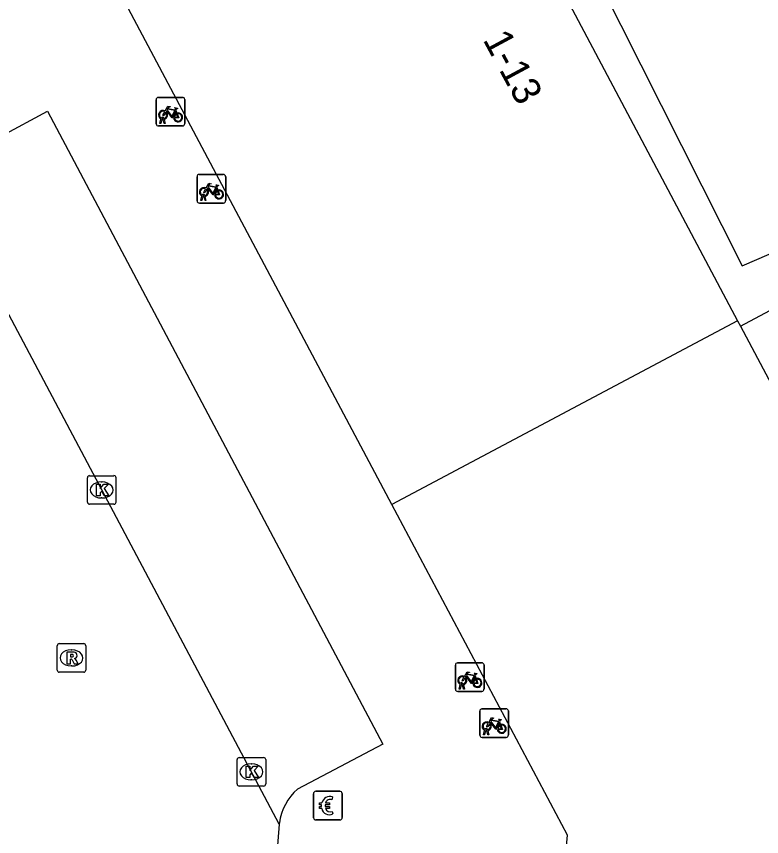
# Model space of a CAD drawing. Extents: x 160304 to 160954, y 383686 to 384161.
# Drawn here: x 160831.95 to 160858.01, y 383857.97 to 383886.65 of the extents above; entities that cross this region are included whole.
import ezdxf

# ---------------------------------------------------------------- set-up
doc = ezdxf.new("R2010")
doc.units = 0
for name, color, linetype in [('IMGEO_Betaalautomaat', 7, 'Continuous'), ('IMGEO_Fietsenrek', 7, 'Continuous'), ('IMGEO_Groenvoorziening', 7, 'Continuous'), ('IMGEO_Kolk', 7, 'Continuous'), ('IMGEO_Pand', 7, 'Continuous'), ('IMGEO_Pand_nummerreeks', 7, 'Continuous'), ('IMGEO_Rijbaan_lokaal_open', 7, 'Continuous'), ('IMGEO_Rioolput', 7, 'Continuous'), ('IMGEO_Voetpad_open', 7, 'Continuous')]:
    doc.layers.add(name, color=color, linetype=linetype)

msp = doc.modelspace()

# ---------------------------------------------------------------- linework, layer by layer
at = {"layer": 'IMGEO_Betaalautomaat'}
for p, q in [((160842.341, 383858.628), (160842.341, 383859.469)), ((160842.341, 383859.469), (160842.341, 383858.628)), ((160842.416, 383859.552), (160843.257, 383859.552)), ((160843.257, 383859.552), (160842.416, 383859.552)), ((160843.34, 383859.478), (160843.34, 383858.637)), ((160843.34, 383858.637), (160843.34, 383859.478)), ((160843.003, 383859.357), (160842.986, 383859.257)), ((160842.624, 383859.016), (160842.624, 383859.084)), ((160842.745, 383859.084), (160842.745, 383859.016)), ((160842.99, 383858.851), (160843.012, 383858.764)), ((160843.266, 383858.553), (160842.425, 383858.553)), ((160842.425, 383858.553), (160843.266, 383858.553))]:
    msp.add_line(p, q, dxfattribs=at)
for points in [[(160842.624, 383859.084), (160842.555, 383859.084), (160842.555, 383859.153), (160842.634, 383859.153)], [(160842.629, 383858.947), (160842.555, 383858.947), (160842.555, 383859.016), (160842.624, 383859.016)], [(160842.756, 383859.153), (160842.903, 383859.153), (160842.903, 383859.084), (160842.745, 383859.084)], [(160842.745, 383859.016), (160842.903, 383859.016), (160842.903, 383858.947), (160842.759, 383858.947)]]:
    msp.add_lwpolyline(points, dxfattribs=at)
for centre, radius, start, end in [((160842.419, 383859.475), 0.0779, 92.4484, 184.2845), ((160842.419, 383859.475), 0.0779, 92.4484, 184.2845), ((160843.263, 383859.475), 0.0779, 2.4484, 94.2845), ((160843.263, 383859.475), 0.0779, 2.4484, 94.2845), ((160842.917, 383859.077), 0.293, 73.014, 165.0139), ((160842.923, 383859.09), 0.179, 69.3236, 159.5683), ((160842.89, 383859.002), 0.267, 191.8096, 297.0389), ((160842.923, 383859.017), 0.179, 202.7625, 291.8693), ((160842.419, 383858.631), 0.0779, 182.4484, 274.2845), ((160842.419, 383858.631), 0.0779, 182.4484, 274.2845), ((160843.263, 383858.631), 0.0779, 272.4484, 4.2845), ((160843.263, 383858.631), 0.0779, 272.4484, 4.2845)]:
    msp.add_arc(centre, radius, start, end, dxfattribs=at)
at = {"layer": 'IMGEO_Fietsenrek'}
for p, q in [((160836.838, 383882.893), (160836.838, 383883.734)), ((160836.838, 383883.734), (160836.838, 383882.893)), ((160836.913, 383883.818), (160837.754, 383883.818)), ((160837.754, 383883.818), (160836.913, 383883.818)), ((160837.838, 383883.743), (160837.838, 383882.902)), ((160837.838, 383882.902), (160837.838, 383883.743)), ((160837.525, 383883.367), (160837.561, 383883.272)), ((160836.965, 383882.902), (160837.004, 383883.062)), ((160837.034, 383883.05), (160836.999, 383882.902)), ((160837.076, 383883.074), (160837.075, 383883.078)), ((160837.117, 383882.902), (160837.083, 383883.044)), ((160837.107, 383883.085), (160837.108, 383883.078)), ((160837.115, 383883.048), (160837.15, 383882.902)), ((160837.763, 383882.818), (160836.922, 383882.818)), ((160836.922, 383882.818), (160837.763, 383882.818)), ((160836.999, 383882.902), (160836.965, 383882.902)), ((160837.15, 383882.902), (160837.117, 383882.902)), ((160838.268, 383880.199), (160838.268, 383881.04)), ((160838.268, 383881.04), (160838.268, 383880.199)), ((160838.343, 383881.124), (160839.184, 383881.124)), ((160839.184, 383881.124), (160838.343, 383881.124)), ((160839.268, 383881.049), (160839.268, 383880.208)), ((160839.268, 383880.208), (160839.268, 383881.049)), ((160838.955, 383880.673), (160838.991, 383880.578)), ((160839.193, 383880.124), (160838.352, 383880.124)), ((160838.352, 383880.124), (160839.193, 383880.124)), ((160838.395, 383880.208), (160838.434, 383880.368)), ((160838.429, 383880.208), (160838.395, 383880.208)), ((160838.464, 383880.356), (160838.429, 383880.208)), ((160838.506, 383880.38), (160838.505, 383880.384)), ((160838.547, 383880.208), (160838.513, 383880.35)), ((160838.537, 383880.391), (160838.538, 383880.384)), ((160838.545, 383880.354), (160838.58, 383880.208)), ((160838.58, 383880.208), (160838.547, 383880.208)), ((160847.303, 383863.121), (160847.303, 383863.962)), ((160847.303, 383863.962), (160847.303, 383863.121)), ((160847.378, 383864.046), (160848.219, 383864.046)), ((160848.219, 383864.046), (160847.378, 383864.046)), ((160848.303, 383863.971), (160848.303, 383863.13)), ((160848.303, 383863.13), (160848.303, 383863.971)), ((160847.99, 383863.595), (160848.026, 383863.5)), ((160847.43, 383863.13), (160847.469, 383863.29)), ((160847.499, 383863.278), (160847.464, 383863.13)), ((160847.541, 383863.302), (160847.54, 383863.306)), ((160847.582, 383863.13), (160847.548, 383863.272)), ((160847.572, 383863.313), (160847.573, 383863.306)), ((160847.58, 383863.276), (160847.615, 383863.13)), ((160848.228, 383863.046), (160847.387, 383863.046)), ((160847.387, 383863.046), (160848.228, 383863.046)), ((160847.464, 383863.13), (160847.43, 383863.13)), ((160847.615, 383863.13), (160847.582, 383863.13)), ((160848.156, 383861.513), (160848.156, 383862.354)), ((160848.156, 383862.354), (160848.156, 383861.513)), ((160848.231, 383862.438), (160849.072, 383862.438)), ((160849.072, 383862.438), (160848.231, 383862.438)), ((160849.156, 383862.363), (160849.156, 383861.522)), ((160849.156, 383861.522), (160849.156, 383862.363)), ((160848.843, 383861.987), (160848.879, 383861.892)), ((160848.283, 383861.522), (160848.322, 383861.682)), ((160848.317, 383861.522), (160848.283, 383861.522)), ((160848.352, 383861.67), (160848.317, 383861.522)), ((160848.394, 383861.694), (160848.393, 383861.698)), ((160848.435, 383861.522), (160848.401, 383861.664)), ((160848.425, 383861.705), (160848.426, 383861.698)), ((160848.433, 383861.668), (160848.468, 383861.522)), ((160848.468, 383861.522), (160848.435, 383861.522)), ((160849.081, 383861.438), (160848.24, 383861.438)), ((160848.24, 383861.438), (160849.081, 383861.438))]:
    msp.add_line(p, q, dxfattribs=at)
for points in [[(160837.172, 383883.292), (160837.12, 383883.202), (160837.08, 383883.177), (160837.081, 383883.224), (160837.136, 383883.318)], [(160837.151, 383883.344), (160837.246, 383883.508), (160837.332, 383883.494), (160837.334, 383883.485), (160837.278, 383883.474), (160837.251, 383883.429), (160837.507, 383883.388)], [(160837.447, 383883.1), (160837.397, 383883.1), (160837.206, 383883.351), (160837.187, 383883.319)], [(160837.494, 383883.363), (160837.237, 383883.404), (160837.22, 383883.375), (160837.387, 383883.155), (160837.494, 383883.363)], [(160837.542, 383883.265), (160837.512, 383883.342), (160837.403, 383883.124), (160837.446, 383883.124)], [(160837.507, 383883.388), (160837.532, 383883.437), (160837.526, 383883.441), (160837.503, 383883.445), (160837.491, 383883.452), (160837.49, 383883.455), (160837.492, 383883.46), (160837.587, 383883.445), (160837.589, 383883.435), (160837.579, 383883.422), (160837.567, 383883.416), (160837.553, 383883.422), (160837.525, 383883.367)], [(160837.476, 383883.124), (160837.596, 383883.123), (160837.552, 383883.237)], [(160837.572, 383883.244), (160837.627, 383883.099), (160837.477, 383883.099)], [(160838.581, 383880.65), (160838.676, 383880.814), (160838.762, 383880.8), (160838.764, 383880.791), (160838.708, 383880.78), (160838.681, 383880.735), (160838.937, 383880.694)], [(160838.924, 383880.669), (160838.667, 383880.71), (160838.65, 383880.681), (160838.817, 383880.461), (160838.924, 383880.669)], [(160838.937, 383880.694), (160838.962, 383880.743), (160838.956, 383880.747), (160838.933, 383880.751), (160838.921, 383880.758), (160838.92, 383880.761), (160838.922, 383880.766), (160839.017, 383880.751), (160839.019, 383880.741), (160839.009, 383880.728), (160838.997, 383880.722), (160838.983, 383880.728), (160838.955, 383880.673)], [(160838.602, 383880.598), (160838.55, 383880.508), (160838.51, 383880.483), (160838.511, 383880.53), (160838.566, 383880.624)], [(160838.877, 383880.406), (160838.827, 383880.406), (160838.636, 383880.657), (160838.617, 383880.625)], [(160838.972, 383880.571), (160838.942, 383880.648), (160838.833, 383880.43), (160838.876, 383880.43)], [(160838.906, 383880.43), (160839.026, 383880.429), (160838.982, 383880.543)], [(160839.002, 383880.55), (160839.057, 383880.405), (160838.907, 383880.405)], [(160847.637, 383863.52), (160847.585, 383863.43), (160847.545, 383863.405), (160847.546, 383863.452), (160847.601, 383863.546)], [(160847.616, 383863.572), (160847.711, 383863.736), (160847.797, 383863.722), (160847.799, 383863.713), (160847.743, 383863.702), (160847.716, 383863.657), (160847.972, 383863.616)], [(160847.912, 383863.328), (160847.862, 383863.328), (160847.671, 383863.579), (160847.652, 383863.547)], [(160847.959, 383863.591), (160847.702, 383863.632), (160847.685, 383863.603), (160847.852, 383863.383), (160847.959, 383863.591)], [(160848.007, 383863.493), (160847.977, 383863.57), (160847.868, 383863.352), (160847.911, 383863.352)], [(160847.972, 383863.616), (160847.997, 383863.665), (160847.991, 383863.669), (160847.968, 383863.673), (160847.956, 383863.68), (160847.955, 383863.683), (160847.957, 383863.688), (160848.052, 383863.673), (160848.054, 383863.663), (160848.044, 383863.65), (160848.032, 383863.644), (160848.018, 383863.65), (160847.99, 383863.595)], [(160847.941, 383863.352), (160848.061, 383863.351), (160848.017, 383863.465)], [(160848.037, 383863.472), (160848.092, 383863.327), (160847.942, 383863.327)], [(160848.469, 383861.964), (160848.564, 383862.128), (160848.65, 383862.114), (160848.652, 383862.105), (160848.596, 383862.094), (160848.569, 383862.049), (160848.825, 383862.008)], [(160848.825, 383862.008), (160848.85, 383862.057), (160848.844, 383862.061), (160848.821, 383862.065), (160848.809, 383862.072), (160848.808, 383862.075), (160848.81, 383862.08), (160848.905, 383862.065), (160848.907, 383862.055), (160848.897, 383862.042), (160848.885, 383862.036), (160848.871, 383862.042), (160848.843, 383861.987)], [(160848.49, 383861.912), (160848.438, 383861.822), (160848.398, 383861.797), (160848.399, 383861.844), (160848.454, 383861.938)], [(160848.765, 383861.72), (160848.715, 383861.72), (160848.524, 383861.971), (160848.505, 383861.939)], [(160848.812, 383861.983), (160848.555, 383862.024), (160848.538, 383861.995), (160848.705, 383861.775), (160848.812, 383861.983)], [(160848.86, 383861.885), (160848.83, 383861.962), (160848.721, 383861.744), (160848.764, 383861.744)], [(160848.794, 383861.744), (160848.914, 383861.743), (160848.87, 383861.857)], [(160848.89, 383861.864), (160848.945, 383861.719), (160848.795, 383861.719)]]:
    msp.add_lwpolyline(points, dxfattribs=at)
for centre, radius, start, end in [((160836.916, 383883.74), 0.0779, 92.4484, 184.2845), ((160836.916, 383883.74), 0.0779, 92.4484, 184.2845), ((160837.76, 383883.74), 0.0779, 2.4484, 94.2845), ((160837.76, 383883.74), 0.0779, 2.4484, 94.2845), ((160837.078, 383883.203), 0.159, 62.6766, 242.1369), ((160837.078, 383883.203), 0.129, 63.3192, 238.903), ((160837.078, 383883.203), 0.129, 283.6043, 43.4302), ((160837.078, 383883.203), 0.159, 283.5766, 46.6042), ((160837.605, 383883.119), 0.159, 187.0065, 105.7708), ((160837.058, 383883.074), 0.0499, 12.8025, 158.6934), ((160837.078, 383883.203), 0.159, 253.9967, 271.7867), ((160837.058, 383883.074), 0.0174, 12.8025, 163.4502), ((160837.078, 383883.203), 0.129, 253.415, 269.0204), ((160837.605, 383883.119), 0.159, 113.3408, 178.3217), ((160837.605, 383883.119), 0.129, 113.923, 177.9556), ((160837.605, 383883.119), 0.129, 188.6715, 104.5883), ((160836.916, 383882.896), 0.0779, 182.4484, 274.2845), ((160836.916, 383882.896), 0.0779, 182.4484, 274.2845), ((160837.76, 383882.896), 0.0779, 272.4484, 4.2845), ((160837.76, 383882.896), 0.0779, 272.4484, 4.2845), ((160838.346, 383881.046), 0.0779, 92.4484, 184.2845), ((160838.346, 383881.046), 0.0779, 92.4484, 184.2845), ((160839.19, 383881.046), 0.0779, 2.4484, 94.2845), ((160839.19, 383881.046), 0.0779, 2.4484, 94.2845), ((160838.508, 383880.509), 0.159, 62.6766, 242.1369), ((160838.508, 383880.509), 0.129, 63.3192, 238.903), ((160838.488, 383880.38), 0.0499, 12.8025, 158.6934), ((160838.508, 383880.509), 0.129, 283.6043, 43.4302), ((160838.508, 383880.509), 0.159, 283.5766, 46.6042), ((160839.035, 383880.425), 0.159, 113.3408, 178.3217), ((160839.035, 383880.425), 0.159, 187.0065, 105.7708), ((160839.035, 383880.425), 0.129, 113.923, 177.9556), ((160839.035, 383880.425), 0.129, 188.6715, 104.5883), ((160838.346, 383880.202), 0.0779, 182.4484, 274.2845), ((160838.346, 383880.202), 0.0779, 182.4484, 274.2845), ((160838.508, 383880.509), 0.159, 253.9967, 271.7867), ((160838.488, 383880.38), 0.0174, 12.8025, 163.4502), ((160838.508, 383880.509), 0.129, 253.415, 269.0204), ((160839.19, 383880.202), 0.0779, 272.4484, 4.2845), ((160839.19, 383880.202), 0.0779, 272.4484, 4.2845), ((160847.381, 383863.968), 0.0779, 92.4484, 184.2845), ((160847.381, 383863.968), 0.0779, 92.4484, 184.2845), ((160848.225, 383863.968), 0.0779, 2.4484, 94.2845), ((160848.225, 383863.968), 0.0779, 2.4484, 94.2845), ((160847.543, 383863.431), 0.159, 62.6766, 242.1369), ((160847.543, 383863.431), 0.129, 63.3192, 238.903), ((160847.543, 383863.431), 0.129, 283.6043, 43.4302), ((160847.543, 383863.431), 0.159, 283.5766, 46.6042), ((160848.07, 383863.347), 0.159, 113.3408, 178.3217), ((160848.07, 383863.347), 0.159, 187.0065, 105.7708), ((160847.523, 383863.302), 0.0499, 12.8025, 158.6934), ((160847.543, 383863.431), 0.159, 253.9967, 271.7867), ((160847.523, 383863.302), 0.0174, 12.8025, 163.4502), ((160847.543, 383863.431), 0.129, 253.415, 269.0204), ((160848.07, 383863.347), 0.129, 113.923, 177.9556), ((160848.07, 383863.347), 0.129, 188.6715, 104.5883), ((160847.381, 383863.124), 0.0779, 182.4484, 274.2845), ((160847.381, 383863.124), 0.0779, 182.4484, 274.2845), ((160848.225, 383863.124), 0.0779, 272.4484, 4.2845), ((160848.225, 383863.124), 0.0779, 272.4484, 4.2845), ((160848.234, 383862.36), 0.0779, 92.4484, 184.2845), ((160848.234, 383862.36), 0.0779, 92.4484, 184.2845), ((160849.078, 383862.36), 0.0779, 2.4484, 94.2845), ((160849.078, 383862.36), 0.0779, 2.4484, 94.2845), ((160848.396, 383861.823), 0.159, 62.6766, 242.1369), ((160848.396, 383861.823), 0.129, 63.3192, 238.903), ((160848.396, 383861.823), 0.129, 283.6043, 43.4302), ((160848.396, 383861.823), 0.159, 283.5766, 46.6042), ((160848.923, 383861.739), 0.159, 113.3408, 178.3217), ((160848.923, 383861.739), 0.159, 187.0065, 105.7708), ((160848.923, 383861.739), 0.129, 113.923, 177.9556), ((160848.923, 383861.739), 0.129, 188.6715, 104.5883), ((160848.234, 383861.516), 0.0779, 182.4484, 274.2845), ((160848.234, 383861.516), 0.0779, 182.4484, 274.2845), ((160848.376, 383861.694), 0.0499, 12.8025, 158.6934), ((160848.396, 383861.823), 0.159, 253.9967, 271.7867), ((160848.376, 383861.694), 0.0174, 12.8025, 163.4502), ((160848.396, 383861.823), 0.129, 253.415, 269.0204), ((160849.078, 383861.516), 0.0779, 272.4484, 4.2845), ((160849.078, 383861.516), 0.0779, 272.4484, 4.2845)]:
    msp.add_arc(centre, radius, start, end, dxfattribs=at)
at = {"layer": 'IMGEO_Groenvoorziening'}
for points in [[(160850.413, 383904.764), (160857.898, 383890.588), (160852.372, 383887.768), (160857.334, 383877.933), (160869.118, 383883.019), (160866.077, 383895.016)], [(160857.274, 383875.816), (160862.472, 383878.595), (160870.895, 383862.33), (160867.154, 383826.483), (160854.767, 383810.821), (160851.843, 383813.196)]]:
    msp.add_lwpolyline(points, dxfattribs=at)
at = {"layer": 'IMGEO_Kolk'}
for p, q in [((160834.431, 383869.664), (160834.431, 383870.516)), ((160834.506, 383870.59), (160835.358, 383870.59)), ((160834.919, 383870.37), (160834.944, 383870.37)), ((160835.432, 383870.516), (160835.432, 383869.664)), ((160834.942, 383869.81), (160834.917, 383869.81)), ((160835.358, 383869.59), (160834.506, 383869.59)), ((160839.667, 383859.809), (160839.667, 383860.661)), ((160839.742, 383860.735), (160840.594, 383860.735)), ((160840.668, 383860.661), (160840.668, 383859.809)), ((160840.155, 383860.515), (160840.18, 383860.515)), ((160840.178, 383859.955), (160840.153, 383859.955)), ((160840.594, 383859.735), (160839.742, 383859.735))]:
    msp.add_line(p, q, dxfattribs=at)
for points in [[(160834.431, 383869.664), (160834.431, 383870.516)], [(160834.506, 383870.59), (160835.358, 383870.59)], [(160835.432, 383870.516), (160835.432, 383869.664)], [(160834.752, 383870.29), (160834.875, 383870.29), (160834.875, 383870.139), (160835.005, 383870.29), (160835.169, 383870.29), (160835.023, 383870.139), (160835.176, 383869.89), (160835.024, 383869.89), (160834.939, 383870.054), (160834.875, 383869.987), (160834.875, 383869.89), (160834.752, 383869.89), (160834.752, 383870.29)], [(160835.358, 383869.59), (160834.506, 383869.59)], [(160839.667, 383859.809), (160839.667, 383860.661)], [(160839.742, 383860.735), (160840.594, 383860.735)], [(160840.668, 383860.661), (160840.668, 383859.809)], [(160839.988, 383860.435), (160840.111, 383860.435), (160840.111, 383860.284), (160840.241, 383860.435), (160840.405, 383860.435), (160840.259, 383860.284), (160840.412, 383860.035), (160840.26, 383860.035), (160840.175, 383860.199), (160840.111, 383860.132), (160840.111, 383860.035), (160839.988, 383860.035), (160839.988, 383860.435)], [(160840.594, 383859.735), (160839.742, 383859.735)]]:
    msp.add_lwpolyline(points, dxfattribs=at)
for centre, start, end in [((160834.508, 383870.514), 91.552, 178.448), ((160834.508, 383870.514), 91.552, 178.448), ((160835.356, 383870.514), 1.552, 88.448), ((160835.356, 383870.514), 1.552, 88.448), ((160834.508, 383869.666), 181.552, 268.448), ((160834.508, 383869.666), 181.552, 268.448), ((160835.356, 383869.666), 271.552, 358.448), ((160835.356, 383869.666), 271.552, 358.448), ((160839.744, 383860.659), 91.552, 178.448), ((160839.744, 383860.659), 91.552, 178.448), ((160840.592, 383860.659), 1.552, 88.448), ((160840.592, 383860.659), 1.552, 88.448), ((160839.744, 383859.811), 181.552, 268.448), ((160839.744, 383859.811), 181.552, 268.448), ((160840.592, 383859.811), 271.552, 358.448), ((160840.592, 383859.811), 271.552, 358.448)]:
    msp.add_arc(centre, 0.0765, start, end, dxfattribs=at)
for centre, major_axis, ratio, start_param, end_param in [((160834.918, 383870.09), (-0.387, 0.002), 0.722429, 4.712389, 7.853982), ((160834.943, 383870.09), (-0.39, 0.002), 0.717154, 1.570796, 4.712389), ((160840.154, 383860.235), (-0.387, 0.002), 0.722429, 4.712389, 7.853982), ((160840.179, 383860.235), (-0.39, 0.002), 0.717154, 1.570796, 4.712389)]:
    msp.add_ellipse(centre, major_axis=major_axis, ratio=ratio, start_param=start_param, end_param=end_param, dxfattribs=at)
at = {"layer": 'IMGEO_Pand'}
for points in [[(160845.08, 383869.587), (160835.078, 383888.424)], [(160850.579, 383888.426), (160857.172, 383876.008)], [(160857.172, 383876.008), (160845.08, 383869.587)], [(160857.172, 383876.008), (160857.274, 383875.816)], [(160857.274, 383875.816), (160863.179, 383864.695), (160864.295, 383864.926), (160865.99, 383856.743), (160864.863, 383856.51), (160863.738, 383843.778)], [(160846.911, 383845.265), (160847.603, 383853.097), (160850.344, 383854.648), (160850.918, 383854.597), (160851.22, 383858.023), (160845.08, 383869.587)]]:
    msp.add_lwpolyline(points, dxfattribs=at)
at = {"layer": 'IMGEO_Rijbaan_lokaal_open'}
for points in [[(160841.141, 383858.403), (160829.033, 383881.187)], [(160841.141, 383858.403), (160840.858, 383854.826), (160840.538, 383851.736)]]:
    msp.add_lwpolyline(points, dxfattribs=at)
at = {"layer": 'IMGEO_Rioolput'}
for p, q in [((160833.375, 383863.79), (160833.375, 383864.642)), ((160833.45, 383864.716), (160834.302, 383864.716)), ((160834.376, 383864.642), (160834.376, 383863.79)), ((160833.863, 383864.496), (160833.888, 383864.496)), ((160833.886, 383863.936), (160833.861, 383863.936)), ((160834.302, 383863.716), (160833.45, 383863.716))]:
    msp.add_line(p, q, dxfattribs=at)
for points in [[(160833.375, 383863.79), (160833.375, 383864.642)], [(160833.45, 383864.716), (160834.302, 383864.716)], [(160834.376, 383864.642), (160834.376, 383863.79)], [(160833.964, 383864.414), (160833.712, 383864.416), (160833.712, 383864.016)], [(160833.712, 383864.016), (160833.836, 383864.016), (160833.836, 383864.178), (160833.847, 383864.178)], [(160833.89, 383864.335), (160833.836, 383864.335), (160833.836, 383864.254)], [(160833.836, 383864.254), (160833.888, 383864.254)], [(160833.894, 383864.149), (160833.965, 383864.016), (160834.105, 383864.016), (160834.04, 383864.142)], [(160834.302, 383863.716), (160833.45, 383863.716)]]:
    msp.add_lwpolyline(points, dxfattribs=at)
for centre, radius, start, end in [((160833.452, 383864.64), 0.0765, 91.552, 178.448), ((160833.452, 383864.64), 0.0765, 91.552, 178.448), ((160834.3, 383864.64), 0.0765, 1.552, 88.448), ((160834.3, 383864.64), 0.0765, 1.552, 88.448), ((160833.963, 383864.304), 0.109, 350.3612, 89.416), ((160833.846, 383864.125), 0.0533, 26.0293, 88.6989), ((160833.872, 383864.443), 0.19, 274.7715, 282.9687), ((160833.896, 383864.239), 0.0964, 77.0061, 93.1865), ((160833.91, 383864.296), 0.0378, 276.6634, 79.6772), ((160833.961, 383864.304), 0.112, 277.5842, 350.9817), ((160833.945, 383864.089), 0.108, 29.5134, 73.7905), ((160833.452, 383863.792), 0.0765, 181.552, 268.448), ((160833.452, 383863.792), 0.0765, 181.552, 268.448), ((160834.3, 383863.792), 0.0765, 271.552, 358.448), ((160834.3, 383863.792), 0.0765, 271.552, 358.448)]:
    msp.add_arc(centre, radius, start, end, dxfattribs=at)
for centre, major_axis, ratio, start_param, end_param in [((160833.862, 383864.216), (-0.387, 0.002), 0.722429, 4.712389, 7.853982), ((160833.887, 383864.216), (-0.39, 0.002), 0.717154, 1.570796, 4.712389)]:
    msp.add_ellipse(centre, major_axis=major_axis, ratio=ratio, start_param=start_param, end_param=end_param, dxfattribs=at)
at = {"layer": 'IMGEO_Voetpad_open'}
msp.add_lwpolyline([(160829.832, 383881.61), (160833.041, 383883.331), (160844.764, 383861.196), (160841.779, 383859.624), (160841.656, 383859.506), (160841.544, 383859.377), (160841.444, 383859.239), (160841.356, 383859.092), (160841.282, 383858.938), (160841.222, 383858.778), (160841.177, 383858.614), (160841.146, 383858.446), (160841.141, 383858.403)], dxfattribs=at)

# ---------------------------------------------------------------- texts
at = {"layer": 'IMGEO_Pand_nummerreeks'}
msp.add_text('1-13', height=1, rotation=298.3234, dxfattribs=at).set_placement((160848.248, 383885.839))

doc.saveas('drawing.dxf')
